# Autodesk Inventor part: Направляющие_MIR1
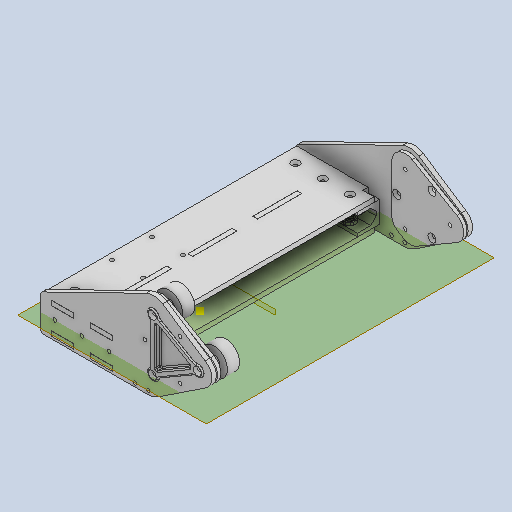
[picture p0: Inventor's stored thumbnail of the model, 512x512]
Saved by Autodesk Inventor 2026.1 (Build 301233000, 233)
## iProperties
Created: 2025-12
Part Number: Направляющие_MIR1
Material: Типовые
Document SubType Name: Modeling
Designer: Yury Melnikov
Density: 1 g/cm^3
Appearance: По умолчанию
Author: Yury Melnikov
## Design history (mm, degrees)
derived "Направляющие.ipt"
  sketch "Эскиз1"
    geometry: L1 (0, 0)-(-16, 0) reference; L2 (-16, 0)-(-16, -200) reference; L3 (-16, -200)-(0, -200) reference; L4 (0, -200)-(0, 0) reference; 1 further point
  sketch "Эскиз2"
    geometry: 1 further point
  sketch "Эскиз3"
    geometry: L1 (0, 0)-(0, -200) reference; L2 (16, -200)-(16, 0) reference; L3 (28.3, -33.725)-(-12.3, -10.284) reference; L4 (-12.3, -10.284)-(-12.3, -57.165) reference; L5 (-12.3, -57.165)-(28.3, -33.725) reference; C1 r 12.3 at (28.3, -33.725) reference; C2 r 12.3 at (-12.3, -10.284) reference; C3 r 12.3 at (-12.3, -57.165) reference; 1 further point
    constraints: 1 other
  sketch "Эскиз4"
    geometry: C1 r 12.3 at (0, 0) reference; C2 r 12.3 at (-40.6, 23.44) reference; C3 r 12.3 at (-40.6, -23.44) reference; C4 r 4 at (0, 0) reference; C5 r 4 at (-40.6, 23.44) reference; C6 r 4 at (-40.6, -23.44) reference; 1 further point
  sketch "Эскиз5"
    geometry: L1 (6.15, 10.652)-(-34.45, 34.093) reference; L2 (-52.9, 23.44)-(-52.9, -23.44) reference; L3 (-34.45, -34.093)-(6.15, -10.652) reference; A1 r 12.3 centre (-40.6, -23.44) between (-34.45, -34.093) and (-52.9, -23.44) reference; A2 r 12.3 centre (-40.6, 23.44) between (-52.9, 23.44) and (-34.45, 34.093) reference; A3 r 12.3 centre (0, 0) between (6.15, -10.652) and (6.15, 10.652) reference; 1 further point
  sketch "Эскиз6"
    geometry: L1 (0, 0)-(-40.6, 23.44) reference; L2 (-40.6, 23.44)-(-40.6, -23.44) reference; L3 (-40.6, -23.44)-(0, 0) reference; L4 (-35.6, 23.44)-(-2.5, 4.33) reference; L5 (-2.5, -4.33)-(-35.6, -23.44) reference; L6 (-43.1, -19.11)-(-43.1, 19.11) reference; L7 (-38.1, 19.11)-(-5, 0) reference; L8 (-5, 0)-(-38.1, -19.11) reference; L9 (-38.1, -19.11)-(-38.1, 19.11) reference; C1 r 12.3 at (-40.6, 23.44) reference; C2 r 12.3 at (-40.6, -23.44) reference; C3 r 12.3 at (0, 0) reference; C4 r 1.6 at (0, 0) reference; C5 r 1.6 at (-40.6, 23.44) reference; C6 r 1.6 at (-40.6, -23.44) reference; A1 r 5 centre (-40.6, 23.44) between (-35.6, 23.44) and (-43.1, 19.11) reference; A2 r 5 centre (0, 0) between (-2.5, -4.33) and (-2.5, 4.33) reference; A3 r 5 centre (-40.6, -23.44) between (-43.1, -19.11) and (-35.6, -23.44) reference; 3 further points
    constraints: 2 other
  sketch "Эскиз7"
    geometry: C1 r 1.6 at (-40.6, 23.44) reference; C2 r 1.6 at (0, 0) reference; C3 r 1.6 at (-40.6, -23.44) reference; 1 further point
  sketch "Эскиз8"
    geometry: L1 (-4.478, 5.472)-(-33.622, 22.298) reference; L2 (-43.1, 16.826)-(-43.1, -16.826) reference; L3 (-33.622, -22.298)-(-4.478, -5.472) reference; L4 (-34.45, 34.093)-(6.15, 10.652) reference; L5 (6.15, -10.652)-(-34.45, -34.093) reference; L6 (-52.9, -23.44)-(-52.9, 23.44) reference; L7 (-30, -82.992)-(-34, -82.992) reference; L8 (-28.3, 33.725)-(-28.3, -166.275) reference; L9 (-142.9, -11.74)-(-142.9, -38.74) reference; L10 (-139.9, -41.74)-(-46.638, -41.74) reference; L11 (-35.571, -38.399)-(6.806, -10.245) reference; L12 (-34.45, 34.093)-(6.15, 10.652) reference; L13 (6.15, 10.652)-(-32.359, 35.974) reference; L14 (-141.217, -9.045)-(-47.187, 36.917) reference; A1 r 5 centre (-1.978, -9.802) between (-0.989, -4.901) and (-4.478, -5.472) reference; A2 r 5 centre (0, 0) between (-0.989, -4.901) and (-0.989, 4.901) reference; A3 r 5 centre (-1.978, 9.802) between (-4.478, 5.472) and (-0.989, 4.901) reference; A4 r 5 centre (-31.122, 26.628) between (-35.861, 25.034) and (-33.622, 22.298) reference; A5 r 5 centre (-40.6, 23.44) between (-35.861, 25.034) and (-44.35, 20.133) reference; A6 r 5 centre (-48.1, 16.826) between (-43.1, 16.826) and (-44.35, 20.133) reference; A7 r 5 centre (-48.1, -16.826) between (-44.35, -20.133) and (-43.1, -16.826) reference; A8 r 5 centre (-40.6, -23.44) between (-44.35, -20.133) and (-35.861, -25.034) reference; A9 r 5 centre (-31.122, -26.628) between (-33.622, -22.298) and (-35.861, -25.034) reference; A10 r 12.3 centre (-40.6, 23.44) between (-34.45, 34.093) and (-52.9, 23.44) reference; A11 r 12.3 centre (0, 0) between (6.15, -10.652) and (6.15, 10.652) reference; A12 r 12.3 centre (-40.6, -23.44) between (-52.9, -23.44) and (-34.45, -34.093) reference; A13 r 12.3 centre (0, 0) between (6.15, -10.652) and (6.15, 10.652) reference; A14 r 12.3 centre (-40.6, 23.44) between (-34.45, 34.093) and (-52.9, 23.44) reference; A15 r 20 centre (-46.638, -21.74) between (-46.638, -41.74) and (-35.571, -38.399) reference; A16 r 3 centre (-139.9, -11.74) between (-141.217, -9.045) and (-142.9, -11.74) reference; A17 r 3 centre (-139.9, -38.74) between (-142.9, -38.74) and (-139.9, -41.74) reference; A18 r 15 centre (-40.6, 23.44) between (-28.3, 14.855) and (-26.541, 18.21) reference; A19 r 15 centre (-40.6, 23.44) between (-32.359, 35.974) and (-47.187, 36.917) reference; 5 further points
  sketch "Эскиз17"
    geometry: L1 (-15.8, 7.674)-(-15.8, 4.326) reference; L2 (-15.8, 4.326)-(-12.9, 2.651) reference; L3 (-12.9, 2.651)-(-10, 4.326) reference; L4 (-10, 4.326)-(-10, 7.674) reference; L5 (-10, 7.674)-(-12.9, 9.349) reference; L6 (-12.9, 9.349)-(-15.8, 7.674) reference; L7 (-12.9, 0.342)-(-17.8, 3.171) reference; L8 (-17.8, 3.171)-(-17.8, 8.829) reference; L9 (-17.8, 8.829)-(-12.9, 11.658) reference; L10 (-12.9, 11.658)-(-8, 8.829) reference; L11 (-8, 8.829)-(-8, 3.171) reference; L12 (-8, 3.171)-(-12.9, 0.342) reference; L13 (0, 0)-(0, 12) reference; L14 (0, 17)-(-74.98, 17) reference; L15 (-32.59, 8.829)-(-32.59, 3.171) reference; L16 (-34.59, 4.326)-(-34.59, 7.674) reference; L17 (-37.49, 2.651)-(-34.59, 4.326) reference; L18 (-37.49, 11.658)-(-32.59, 8.829) reference; L19 (-32.59, 3.171)-(-37.49, 0.342) reference; L20 (-34.59, 7.674)-(-37.49, 9.349) reference; L21 (-40.39, 4.326)-(-37.49, 2.651) reference; L22 (-40.39, 7.674)-(-40.39, 4.326) reference; L23 (-37.49, 9.349)-(-40.39, 7.674) reference; L24 (-37.49, 0.342)-(-42.39, 3.171) reference; L25 (-42.39, 3.171)-(-42.39, 8.829) reference; L26 (-42.39, 8.829)-(-37.49, 11.658) reference; L27 (-57.18, 8.829)-(-57.18, 3.171) reference; L28 (-59.18, 4.326)-(-59.18, 7.674) reference; L29 (-62.08, 2.651)-(-59.18, 4.326) reference; L30 (-62.08, 11.658)-(-57.18, 8.829) reference; L31 (-57.18, 3.171)-(-62.08, 0.342) reference; L32 (-59.18, 7.674)-(-62.08, 9.349) reference; L33 (-64.98, 4.326)-(-62.08, 2.651) reference; L34 (-64.98, 7.674)-(-64.98, 4.326) reference; L35 (-62.08, 9.349)-(-64.98, 7.674) reference; L36 (-62.08, 0.342)-(-66.98, 3.171) reference; L37 (-66.98, 3.171)-(-66.98, 8.829) reference; L38 (-66.98, 8.829)-(-62.08, 11.658) reference; L39 (-74.98, 0)-(-74.98, 12) reference; 11 further points
    constraints: 1 horizontal, 1 other
  sketch "Эскиз18"
    geometry: L1 (-5.8, 3.349)-(-2.9, 5.023) reference; L2 (-2.9, 5.023)-(0, 3.349) reference; L3 (0, 3.349)-(0, 0) reference; L4 (0, 0)-(-2.9, -1.674) reference; L5 (-2.9, -1.674)-(-5.8, 0) reference; L6 (-5.8, 0)-(-5.8, 3.349) reference; L7 (-5.8, 3.349)-(-5.8, 0) reference; L8 (10, 7.674)-(-64.98, 7.674) reference; C1 r 1.65 at (-2.9, 1.674) reference; C2 r 1.65 at (-27.49, 1.674) reference; C3 r 1.65 at (-52.08, 1.674) reference; C4 r 1.65 at (-76.67, 1.674) reference; 3 further points
    constraints: 1 horizontal
  sketch "Эскиз19"
    geometry: L1 (97.72, -35.54)-(97.72, -39.54) reference; L2 (78.12, -35.54)-(97.72, -35.54) reference; L3 (78.12, -39.54)-(78.12, -35.54) reference; L4 (97.72, -39.54)-(78.12, -39.54) reference; L5 (77.92, -11.54)-(97.92, -11.54) reference; L6 (97.92, -11.54)-(97.92, -15.74) reference; L7 (97.92, -15.74)-(77.92, -15.74) reference; L8 (77.92, -15.74)-(77.92, -11.54) reference; L9 (142.9, -15.74)-(67.92, -15.74) reference; L10 (112.9, -11.54)-(132.9, -11.54) reference; L11 (132.9, -11.54)-(132.9, -15.74) reference; L12 (132.9, -15.74)-(112.9, -15.74) reference; L13 (112.9, -15.74)-(112.9, -11.54) reference; L14 (112.9, -39.74)-(112.9, -35.34) reference; L15 (132.9, -35.34)-(132.9, -39.74) reference; L16 (77.92, -39.74)-(77.92, -35.34) reference; L17 (97.92, -35.34)-(97.92, -39.74) reference; 1 further point
  sketch "Эскиз20"
    geometry: L1 (-39.69, -35)-(-35.29, -35) reference; L2 (-35.29, -35)-(-35.29, -75) reference; L3 (-35.29, -75)-(-39.69, -75) reference; L4 (-39.69, -75)-(-39.69, -35) reference; L5 (-39.69, -94)-(-35.29, -94) reference; L6 (-35.29, -94)-(-35.29, -134) reference; L7 (-35.29, -134)-(-39.69, -134) reference; L8 (-39.69, -134)-(-39.69, -94) reference; L9 (-39.69, -153)-(-35.29, -153) reference; L10 (-35.29, -153)-(-35.29, -193) reference; L11 (-35.29, -193)-(-39.69, -193) reference; L12 (-39.69, -193)-(-39.69, -153) reference; L13 (0, -20)-(-74.98, -20) reference; L14 (0, 0)-(-74.98, 0) reference; L15 (-74.98, -228)-(0, -228) reference; 3 further points
    constraints: 1 vertical
  sketch "Эскиз21"
    geometry: L1 (-39.69, -193)-(-35.29, -193) reference; L2 (-35.29, -193)-(-35.29, -153) reference; L3 (-35.29, -153)-(-39.69, -153) reference; L4 (-39.69, -153)-(-39.69, -193) reference; L5 (-39.69, -134)-(-35.29, -134) reference; L6 (-35.29, -134)-(-35.29, -94) reference; L7 (-35.29, -94)-(-39.69, -94) reference; L8 (-39.69, -94)-(-39.69, -134) reference; L9 (-39.69, -75)-(-35.29, -75) reference; L10 (-35.29, -75)-(-35.29, -35) reference; L11 (-35.29, -35)-(-39.69, -35) reference; L12 (-39.69, -35)-(-39.69, -75) reference; L13 (-74.98, 0)-(0, 0) reference; L14 (0, 0)-(0, -228) reference; L15 (-74.98, -228)-(0, -228) reference; L16 (-74.98, 0)-(-74.98, -228) reference; L17 (-39.59, -74.9)-(-35.39, -74.9) reference; L18 (-35.39, -74.9)-(-35.39, -35.1) reference; L19 (-35.39, -35.1)-(-39.59, -35.1) reference; L20 (-39.59, -35.1)-(-39.59, -74.9) reference; L21 (-39.59, -133.9)-(-35.39, -133.9) reference; L22 (-35.39, -133.9)-(-35.39, -94.1) reference; L23 (-35.39, -94.1)-(-39.59, -94.1) reference; L24 (-39.59, -94.1)-(-39.59, -133.9) reference; L25 (-39.59, -192.9)-(-35.39, -192.9) reference; L26 (-35.39, -192.9)-(-35.39, -153.1) reference; L27 (-35.39, -153.1)-(-39.59, -153.1) reference; L28 (-39.59, -153.1)-(-39.59, -192.9) reference; L29 (0, -20)-(-74.98, -20) reference; L30 (-39.59, -20)-(-35.39, -20) reference; L31 (-35.39, -20)-(-35.39, -208) reference; L32 (-35.39, -208)-(-39.59, -208) reference; L33 (-39.59, -208)-(-39.59, -20) reference; C1 r 1.65 at (-62.08, -14) reference; C2 r 1.65 at (-37.49, -14) reference; C3 r 1.65 at (-12.9, -14) reference; 1 further point
  sketch "Эскиз22"
    geometry: L1 (-39.59, -20)-(-35.39, -20) reference; L2 (-35.39, -20)-(-35.39, -208) reference; L3 (-35.39, -208)-(-39.59, -208) reference; L4 (-39.59, -208)-(-39.59, -20) reference; L5 (0, -20)-(-74.98, -20) reference; L6 (-74.98, -228)-(0, -228) reference; 3 further points
  node "РабПлоскость1"
  node "РабПлоскость2"
  node "РабПлоскость3"
  node "РабПлоскость4"
feature "Твердое тело1::Направляющие.ipt" dims "d0" = 10
feature "Твердое тело2::Направляющие.ipt" dims "d0" = 10
feature "Каретка::Направляющие.ipt" dims "d0" = 10
feature "Рука::Направляющие.ipt" dims "d0" = 10
feature "Основная плита::Направляющие.ipt" dims "d0" = 10
feature "Крепление::Направляющие.ipt" dims "d0" = 10
feature "Ребро жесткости::Направляющие.ipt" dims "d0" = 10
tag "Элемент создания тегов1"
sketch "Эскиз11"
  geometry: L1 (6.806, -10.245)-(-35.571, -38.399) reference; L2 (-46.638, -41.74)-(-139.9, -41.74) reference; L3 (-142.9, -38.74)-(-142.9, -11.74) reference; L4 (-33.622, -22.298)-(-4.478, -5.472) reference; L5 (-4.478, 5.472)-(-33.622, 22.298) reference; L6 (-43.1, 16.826)-(-43.1, -16.826) reference; L7 (-30.967, -35.34)-(-142.9, -35.34) reference; L8 (-37.92, -39.74)-(-142.728, -39.74) reference; L9 (-77.92, -35.34)-(-97.92, -35.34) reference; L10 (-97.92, -35.34)-(-97.92, -39.74) reference; L11 (-97.92, -39.74)-(-77.92, -39.74) reference; L12 (-77.92, -39.74)-(-77.92, -35.34) reference; L13 (-112.9, -35.34)-(-132.9, -35.34) reference; L14 (-132.9, -35.34)-(-132.9, -39.74) reference; L15 (-132.9, -39.74)-(-112.9, -39.74) reference; L16 (-112.9, -39.74)-(-112.9, -35.34) reference; L17 (-32.359, 35.974)-(6.15, 10.652) reference; L18 (-141.217, -9.045)-(-47.187, 36.917) reference; A1 r 12.3 centre (0, 0) between (6.806, -10.245) and (6.15, 10.652) reference; A2 r 20 centre (-46.638, -21.74) between (-46.638, -41.74) and (-35.571, -38.399) reference; A3 r 3 centre (-139.9, -38.74) between (-142.9, -38.74) and (-139.9, -41.74) reference; A4 r 3 centre (-139.9, -11.74) between (-141.217, -9.045) and (-142.9, -11.74) reference; A5 r 5 centre (-1.978, -9.802) between (-0.989, -4.901) and (-4.478, -5.472) reference; A6 r 5 centre (0, 0) between (-0.989, -4.901) and (-0.989, 4.901) reference; A7 r 5 centre (-1.978, 9.802) between (-4.478, 5.472) and (-0.989, 4.901) reference; A8 r 5 centre (-31.122, 26.628) between (-35.861, 25.034) and (-33.622, 22.298) reference; A9 r 5 centre (-40.6, 23.44) between (-35.861, 25.034) and (-44.35, 20.133) reference; A10 r 5 centre (-48.1, 16.826) between (-43.1, 16.826) and (-44.35, 20.133) reference; A11 r 5 centre (-48.1, -16.826) between (-44.35, -20.133) and (-43.1, -16.826) reference; A12 r 5 centre (-40.6, -23.44) between (-44.35, -20.133) and (-35.861, -25.034) reference; A13 r 5 centre (-31.122, -26.628) between (-33.622, -22.298) and (-35.861, -25.034) reference; A14 r 15 centre (-40.6, 23.44) between (-32.359, 35.974) and (-47.187, 36.917) reference; 1 further point
sketch "Эскиз14"
  geometry: L1 (142.9, -35.34)-(67.92, -35.34) reference; L2 (67.92, -35.34)-(67.92, -39.74) reference; L3 (67.92, -39.74)-(142.9, -39.74) reference; L4 (142.9, -39.74)-(142.9, -35.34) reference; L5 (97.92, -35.34)-(77.92, -35.34) reference; L6 (77.92, -39.74)-(97.92, -39.74) reference; L7 (77.92, -35.34)-(77.92, -39.74) reference; L8 (142.9, -38.74)-(142.9, -11.74) reference; 2 further points
sketch "Эскиз15"
  geometry: L1 (-3, 15)-(-3, 11.4) reference; L2 (-3, 11.4)-(-8, 6.4) reference; L3 (-8, 6.4)-(-20, 6.4) reference; L4 (-20, 6.4)-(-20, 3.4) reference; L5 (-20, 3.4)-(0, 3.4) reference; L6 (0, 3.4)-(-228, 3.4) reference; L7 (0, 3.4)-(0, 23) reference; L8 (0, 23)-(-20, 23) reference; L9 (-3, 15)-(-8, 20) reference; L10 (-8, 20)-(-20, 20) reference; L11 (-20, 20)-(-20, 23) reference; 5 further points; 1 other entity
  constraints: 1 other
sketch "Эскиз16"
  geometry: L1 (-67.92, -35.34)-(-142.9, -35.34) reference; L2 (-67.92, -39.74)-(-67.92, -35.34) reference; L3 (-142.9, -39.74)-(-67.92, -39.74) reference; L4 (-142.9, -35.34)-(-142.9, -39.74) reference; L5 (-132.9, -35.34)-(-132.9, -39.74) reference; L6 (-132.9, -39.74)-(-112.9, -39.74) reference; L7 (-112.9, -39.74)-(-112.9, -35.34) reference; L8 (-112.9, -35.34)-(-132.9, -35.34) reference; L9 (-97.92, -35.34)-(-97.92, -39.74) reference; L10 (-97.92, -39.74)-(-77.92, -39.74) reference; L11 (-77.92, -39.74)-(-77.92, -35.34) reference; L12 (-77.92, -35.34)-(-97.92, -35.34) reference; L13 (6.806, -10.245)-(-35.571, -38.399) reference; L14 (-46.638, -41.74)-(-139.9, -41.74) reference; L15 (-142.9, -38.74)-(-142.9, -11.74) reference; L16 (-141.217, -9.045)-(-47.187, 36.917) reference; L17 (-32.359, 35.974)-(6.15, 10.652) reference; L18 (-33.622, -22.298)-(-4.478, -5.472) reference; L19 (-4.478, 5.472)-(-33.622, 22.298) reference; L20 (-43.1, 16.826)-(-43.1, -16.826) reference; L21 (-97.72, -39.54)-(-97.72, -35.54) reference; L22 (-97.72, -35.54)-(-78.12, -35.54) reference; L23 (-78.12, -35.54)-(-78.12, -39.54) reference; L24 (-78.12, -39.54)-(-97.72, -39.54) reference; L25 (-113.1, -35.54)-(-113.1, -39.54) reference; L26 (-113.1, -39.54)-(-132.7, -39.54) reference; L27 (-132.7, -39.54)-(-132.7, -35.54) reference; L28 (-132.7, -35.54)-(-113.1, -35.54) reference; A1 r 12.3 centre (0, 0) between (6.806, -10.245) and (6.15, 10.652) reference; A2 r 20 centre (-46.638, -21.74) between (-46.638, -41.74) and (-35.571, -38.399) reference; A3 r 3 centre (-139.9, -38.74) between (-142.9, -38.74) and (-139.9, -41.74) reference; A4 r 3 centre (-139.9, -11.74) between (-141.217, -9.045) and (-142.9, -11.74) reference; A5 r 15 centre (-40.6, 23.44) between (-32.359, 35.974) and (-47.187, 36.917) reference; A6 r 5 centre (-1.978, -9.802) between (-0.989, -4.901) and (-4.478, -5.472) reference; A7 r 5 centre (0, 0) between (-0.989, -4.901) and (-0.989, 4.901) reference; A8 r 5 centre (-1.978, 9.802) between (-4.478, 5.472) and (-0.989, 4.901) reference; A9 r 5 centre (-31.122, 26.628) between (-35.861, 25.034) and (-33.622, 22.298) reference; A10 r 5 centre (-40.6, 23.44) between (-35.861, 25.034) and (-44.35, 20.133) reference; A11 r 5 centre (-48.1, 16.826) between (-43.1, 16.826) and (-44.35, 20.133) reference; A12 r 5 centre (-48.1, -16.826) between (-44.35, -20.133) and (-43.1, -16.826) reference; A13 r 5 centre (-40.6, -23.44) between (-44.35, -20.133) and (-35.861, -25.034) reference; A14 r 5 centre (-31.122, -26.628) between (-33.622, -22.298) and (-35.861, -25.034) reference; 1 further point
node "Твердое тело1"
node "Твердое тело2"
node "Каретка"
node "Рука"
node "Основная плита"
node "Крепление"
node "Ребро жесткости"
